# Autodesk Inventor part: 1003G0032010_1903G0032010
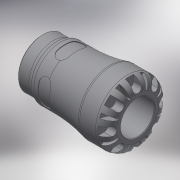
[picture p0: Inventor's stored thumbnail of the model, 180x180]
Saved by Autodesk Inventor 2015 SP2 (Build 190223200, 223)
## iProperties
Created: 2016-12
Part Number: 1003G0032010_1903G0032010
Material: Generic
Description: PLASSON FEMALE ADAPTOR 32X1" SERIES 1
Document SubType Name: Modeling
Designer: KIM
Mass: 664.223 g
Surface Area: 733.008 cm^2
Volume: 474.445 cm^3
Density: 1 g/cm^3
Appearance: Default
Author: KIM
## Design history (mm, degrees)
derived "1003G.ipt"
feature "Solid1::1003G.ipt"
tag "TaggingFeature1"
body "Solid1"
other parameters: "d0" = 79, "d1" = 22.68, "d2" = 32, "d4" = 58, "d6" = 54, "d8" = 49.3, "d13" = 7.2, "d14" = 7.2, "d15" = 0, "d17" = 360 deg, "d19" = 8 deg, "d20" = 0.64, "d21" = 0.64, "d22" = 8 deg, "d24" = 0, "d26" = 360 deg, "d32" = 5.8, "d33" = 5.8, "d39" = 0.90873, "d42" = 30.291, "d43" = 45.24, "d46" = 2.66667, "d47" = 13.5, "d48" = 28.77645, "d50" = 3.795, "d51" = 0.58, "d54" = 11.2, "d55" = 7.04, "d57" = 14.112, "d58" = 0, "d68" = 360 deg, "d72" = 0.64, "d74" = 0, "d76" = 9.52, "d_" = 32, "E_" = 58, "H_" = 79, "l_" = 54, "G_" = 30.291, "l_2" = 13.5, "d9" = 9, "d11" = 58, "d49" = 11.5
